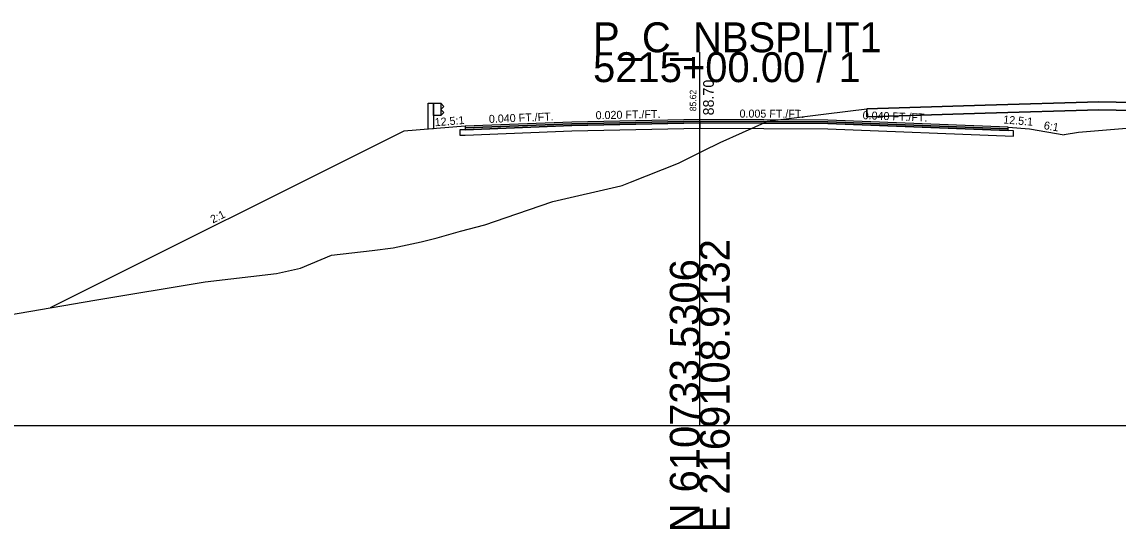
# Model space of a CAD drawing. Extents: x -26 to 1303, y -3010 to 12038.
# Drawn here: x 1086.5 to 1189.2, y 8490.3 to 8537.8 of the extents above; entities that cross this region are included whole.
import ezdxf

# ---------------------------------------------------------------- set-up
doc = ezdxf.new("R2010")
doc.units = 0
for name, color, linetype in [('RD_GPK_XS_Cell', 7, 'Continuous'), ('RD_XS_Base', 7, 'Continuous'), ('RD_XS_ExGround', 7, 'Continuous'), ('RD_XS_ExPaveRet', 7, 'Continuous'), ('RD_XS_GR', 7, 'Continuous'), ('RD_XS_Greenside', 7, 'Continuous'), ('RD_XS_Pave', 7, 'Continuous'), ('RD_XS_PaveOvlay_CP', 7, 'Continuous'), ('RD_XS_TieSlope', 7, 'Continuous'), ('RD_XS_TX_Elev_EX', 7, 'Continuous'), ('RD_XS_TX_Elev_PR', 7, 'Continuous'), ('RD_XS_TX_ShdSlope', 7, 'Continuous'), ('RD_XS_TX_Slope', 7, 'Continuous')]:
    doc.layers.add(name, color=color, linetype=linetype)

msp = doc.modelspace()

# ---------------------------------------------------------------- linework, layer by layer
at = {"layer": 'RD_GPK_XS_Cell'}
for p, q in [((1150, 8500), (1150, 8535)), ((1000, 8500), (1150, 8500)), ((1150, 8500), (1300, 8500))]:
    msp.add_line(p, q, dxfattribs=at)
at = {"layer": 'RD_XS_Base'}
for p, q in [((1138, 8528.14), (1128, 8527.74)), ((1150, 8528.38), (1138, 8528.14)), ((1138, 8527.64), (1150, 8527.88)), ((1150, 8528.38), (1150, 8528.54)), ((1150, 8528.54), (1150, 8527.88)), ((1150, 8528.38), (1150, 8528.38)), ((1150, 8528.38), (1150, 8528.38)), ((1162, 8528.32), (1150, 8528.38)), ((1150, 8527.88), (1150, 8528.38)), ((1150, 8528.38), (1150, 8528.38)), ((1150, 8528.38), (1150, 8528.38)), ((1150, 8527.88), (1150, 8527.88)), ((1150, 8527.88), (1150, 8527.88)), ((1150, 8527.88), (1162, 8527.82)), ((1150, 8527.88), (1150, 8527.88)), ((1178.9, 8527.65), (1162, 8528.32)), ((1164, 8528.24), (1164, 8528.24)), ((1128, 8527.74), (1127.5, 8527.72)), ((1127.5, 8527.72), (1127.5, 8527.22)), ((1127.5, 8527.22), (1128, 8527.24)), ((1127.5, 8527.22), (1127.5, 8527.22)), ((1128, 8527.74), (1128, 8527.74)), ((1128, 8527.74), (1128, 8527.74)), ((1128, 8527.24), (1138, 8527.64)), ((1128, 8527.24), (1128, 8527.24)), ((1138, 8527.64), (1138, 8527.64)), ((1162, 8527.82), (1179.4, 8527.13)), ((1164, 8527.74), (1164, 8527.74)), ((1179.4, 8527.63), (1178.9, 8527.65)), ((1178.9, 8527.65), (1178.9, 8527.65)), ((1179.4, 8527.13), (1179.4, 8527.63)), ((1179.4, 8527.63), (1179.4, 8527.63))]:
    msp.add_line(p, q, dxfattribs=at)
at = {"layer": 'RD_XS_ExGround'}
msp.add_lwpolyline([(1038.53, 8502.37), (1093.3, 8511.75), (1103.65, 8513.47), (1110.34, 8514.26), (1112.57, 8514.75), (1115.47, 8515.97), (1119.31, 8516.43), (1121.27, 8516.67), (1123.9, 8517.23), (1125.38, 8517.62), (1127.59, 8518.24), (1129.87, 8518.81), (1132.85, 8519.86), (1136.23, 8521.02), (1142.59, 8522.48), (1142.72, 8522.51), (1143.5, 8522.82), (1148, 8524.6), (1150.33, 8525.76), (1151.91, 8526.53), (1156.1, 8528.42), (1156.35, 8528.53), (1161.85, 8529.22), (1165.67, 8529.71), (1176.77, 8530.03), (1187.42, 8530.34), (1190.67, 8530.29)], dxfattribs=at)
at = {"layer": 'RD_XS_ExPaveRet'}
for p, q in [((1176.77, 8530.03), (1165.67, 8529.71)), ((1187.42, 8530.34), (1176.77, 8530.03))]:
    msp.add_line(p, q, dxfattribs=at)
for points in [[(1190.67, 8529.54), (1187.42, 8529.59), (1187.42, 8529.59), (1187.42, 8529.59), (1187.42, 8529.59), (1176.77, 8529.28), (1176.77, 8529.28), (1165.67, 8528.96), (1165.67, 8528.96), (1165.67, 8528.96), (1165.67, 8528.96), (1165.67, 8529.71), (1165.67, 8529.71), (1165.67, 8529.71), (1176.77, 8530.03), (1176.77, 8530.03), (1187.42, 8530.34), (1187.42, 8530.34), (1187.42, 8530.34), (1187.42, 8530.34), (1190.67, 8530.29)], [(1165.67, 8529.71), (1165.67, 8528.96), (1176.77, 8529.28), (1187.42, 8529.59), (1190.67, 8529.54), (1202.73, 8529.35), (1202.73, 8530.1), (1190.67, 8530.29), (1187.42, 8530.34)]]:
    msp.add_lwpolyline(points, dxfattribs=at)
at = {"layer": 'RD_XS_GR'}
for p, q in [((1124.56, 8527.79), (1124.56, 8530.22)), ((1124.56, 8530.22), (1124.81, 8530.22)), ((1124.81, 8530.22), (1125.06, 8530.22)), ((1125.06, 8530.22), (1125.06, 8527.83)), ((1125.06, 8529.06), (1125.06, 8530.22)), ((1125.06, 8530.22), (1125.73, 8530.22)), ((1125.73, 8530.22), (1125.73, 8529.06)), ((1125.73, 8530.22), (1125.73, 8530.22)), ((1125.73, 8530.22), (1125.73, 8530.22)), ((1125.73, 8530.22), (1125.73, 8529.06)), ((1126, 8529.93), (1125.73, 8530.22)), ((1125.73, 8529.06), (1125.06, 8529.06)), ((1125.73, 8529.64), (1126, 8529.93)), ((1126, 8529.35), (1125.73, 8529.64)), ((1125.73, 8529.64), (1125.73, 8529.64)), ((1125.73, 8529.06), (1126, 8529.35)), ((1126, 8529.93), (1126, 8529.93)), ((1126, 8529.35), (1126, 8529.35)), ((1125.06, 8527.83), (1124.56, 8527.79))]:
    msp.add_line(p, q, dxfattribs=at)
at = {"layer": 'RD_XS_Greenside'}
for p, q in [((1122.25, 8527.6), (1089.12, 8511.04)), ((1180.9, 8527.81), (1184.15, 8527.26)), ((1185.5, 8527.49), (1184.15, 8527.26))]:
    msp.add_line(p, q, dxfattribs=at)
at = {"layer": 'RD_XS_Pave'}
for p, q in [((1138, 8528.46), (1128, 8528.06)), ((1138, 8528.3), (1128, 8527.9)), ((1128, 8527.9), (1138, 8528.3)), ((1128, 8527.74), (1138, 8528.14)), ((1128, 8528.06), (1128, 8528.06)), ((1128, 8528.06), (1128, 8528.06)), ((1128, 8528.06), (1128, 8527.9)), ((1128, 8527.9), (1128, 8527.9)), ((1128, 8527.9), (1128, 8527.9)), ((1128, 8527.9), (1128, 8527.74)), ((1128, 8527.9), (1128, 8527.9)), ((1150, 8528.7), (1138, 8528.46)), ((1150, 8528.54), (1138, 8528.3)), ((1138, 8528.3), (1150, 8528.54)), ((1138, 8528.14), (1150, 8528.38)), ((1162, 8528.64), (1150, 8528.7)), ((1150, 8528.7), (1150, 8528.7)), ((1150, 8528.7), (1150, 8528.7)), ((1162, 8528.48), (1150, 8528.54)), ((1150, 8528.54), (1150, 8528.54)), ((1150, 8528.54), (1150, 8528.54)), ((1150, 8528.54), (1150, 8528.38)), ((1150, 8528.38), (1150, 8528.54)), ((1150, 8528.54), (1150, 8528.54)), ((1150, 8528.54), (1150, 8528.54)), ((1150, 8528.54), (1150, 8528.54)), ((1150, 8528.54), (1162, 8528.48)), ((1150, 8528.38), (1150, 8528.38)), ((1150, 8528.38), (1162, 8528.32)), ((1150, 8528.38), (1150, 8528.38)), ((1150, 8528.38), (1150, 8528.38)), ((1178.9, 8527.97), (1162, 8528.64)), ((1178.9, 8527.81), (1162, 8528.48)), ((1162, 8528.48), (1178.9, 8527.81)), ((1162, 8528.32), (1178.9, 8527.65)), ((1164, 8528.56), (1164, 8528.56)), ((1164, 8528.4), (1164, 8528.4)), ((1164, 8528.4), (1164, 8528.4)), ((1164, 8528.24), (1164, 8528.24)), ((1178.9, 8527.81), (1178.9, 8527.97)), ((1178.9, 8527.97), (1178.9, 8527.97)), ((1128, 8527.74), (1128, 8527.74)), ((1178.9, 8527.65), (1178.9, 8527.81)), ((1178.9, 8527.81), (1178.9, 8527.81))]:
    msp.add_line(p, q, dxfattribs=at)
at = {"layer": 'RD_XS_PaveOvlay_CP'}
for p, q in [((1138, 8528.46), (1128, 8528.06)), ((1128, 8528.06), (1128, 8528.06)), ((1150, 8528.7), (1138, 8528.46)), ((1162, 8528.64), (1150, 8528.7)), ((1150, 8528.7), (1150, 8528.7)), ((1150, 8528.7), (1150, 8528.7)), ((1178.9, 8527.97), (1162, 8528.64)), ((1164, 8528.56), (1164, 8528.56))]:
    msp.add_line(p, q, dxfattribs=at)
at = {"layer": 'RD_XS_TieSlope'}
for p, q in [((1128, 8528.06), (1122.25, 8527.6)), ((1178.9, 8527.97), (1180.9, 8527.81)), ((1191.5, 8527.97), (1185.5, 8527.49))]:
    msp.add_line(p, q, dxfattribs=at)

# ---------------------------------------------------------------- texts
at = {"layer": 'RD_GPK_XS_Cell'}
for s, p in [('P_C_NBSPLIT1', (1140, 8535)), ('5215+00.00 / 1', (1140, 8532.2))]:
    msp.add_text(s, height=2.8, dxfattribs=at).set_placement(p)
for s, p in [('E 2169108.9132', (1152.8, 8490)), ('N 610733.5306', (1150, 8490))]:
    msp.add_text(s, height=2.8, rotation=90, dxfattribs=at).set_placement(p)
at = {"layer": 'RD_XS_TX_Elev_EX'}
msp.add_text('85.62', height=0.6, rotation=90, dxfattribs=at).set_placement((1149.67, 8529.47))
at = {"layer": 'RD_XS_TX_Elev_PR'}
msp.add_text('88.70', height=1, rotation=90, dxfattribs=at).set_placement((1151.32, 8529.08))
at = {"layer": 'RD_XS_TX_ShdSlope'}
for rotation, p in [(4.5739, (1125.19, 8528.06)), (355.4261, (1178.43, 8528.33))]:
    msp.add_text('12.5:1', height=0.75, rotation=rotation, dxfattribs=at).set_placement(p)
at = {"layer": 'RD_XS_TX_Slope'}
for s, rotation, p in [('0.040 FT./FT.', 2.2906, (1130.25, 8528.37)), ('0.020 FT./FT.', 1.1458, (1140.25, 8528.72)), ('0.005 FT./FT.', 359.7156, (1153.73, 8528.88)), ('0.040 FT./FT.', 357.7094, (1165.26, 8528.73)), ('6:1', 350.5377, (1182.21, 8527.8)), ('2:1', 26.5651, (1104.36, 8518.94))]:
    msp.add_text(s, height=0.75, rotation=rotation, dxfattribs=at).set_placement(p)

doc.saveas('drawing.dxf')
